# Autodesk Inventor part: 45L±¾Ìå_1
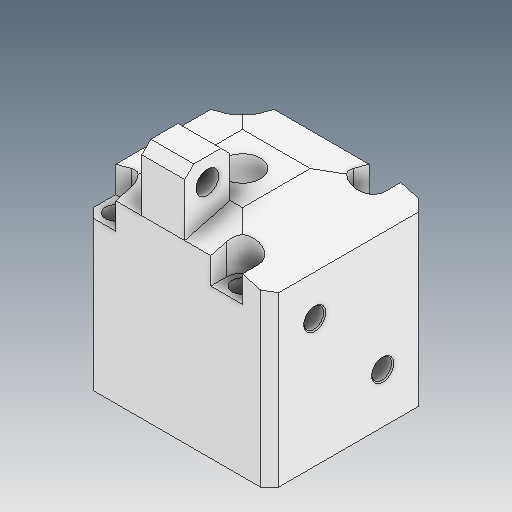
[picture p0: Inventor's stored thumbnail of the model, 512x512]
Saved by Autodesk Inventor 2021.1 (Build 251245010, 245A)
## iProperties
Created: 2021-05
Part Number: 45L±¾Ìå_1
Material: Ogólny
Document SubType Name: Modeling
Designer: user
Density: 1 g/cm^3
Appearance: Domyślna
Author: user
Revision Number: ÈÎºÎ
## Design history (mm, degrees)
feature "ÊäÈë1"
feature "ÊäÈë2"
feature "ÊäÈë3"
feature "ÊäÈë4"
node "Bryła1"
node "Bryła2"
node "Bryła3"
node "Bryła4"
